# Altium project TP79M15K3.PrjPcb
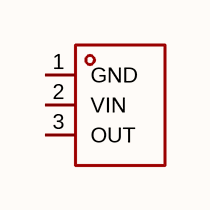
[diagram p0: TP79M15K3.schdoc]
1 sheet, 1 parts. Net scope: global (net labels, ports and power ports of the same name join across sheets).

## Sheet TP79M15K3.schdoc
size 127 x 101 mm

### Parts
U?  tp79m15k3  [TO-252-2_L6.6-W6.1-P4.60-LS9.5-BR]  (value not drawn)

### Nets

Not connected (* = marked no-connect by the designer): U? 1(GND) 2(VIN) 3(OUT)

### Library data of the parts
U? = tp79m15k3: 输出极性:负极;工作电压:30V;输出电压:15V;输出电流:500mA;电源纹波抑制比(PSRR):60dB@(120Hz);输出类型:固定;; Manufacturer: TECH PUBLIC(台舟); AddInBom: yes; ModelId: 9b1bff34ff4c4a46b6b3d16fd76023c5; ModelTransform: 374.015,259.842,0,0,0,0,-43.386,0,0; Output Configuration: 负极; Voltage - Supply: 30V; Output Voltage: 15V; Output Current: 500mA; Voltage Dropout: 2V@(1A); standby current: 2mA; Noise: 200uV; Output Type: 固定; Number of Outputs: 1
